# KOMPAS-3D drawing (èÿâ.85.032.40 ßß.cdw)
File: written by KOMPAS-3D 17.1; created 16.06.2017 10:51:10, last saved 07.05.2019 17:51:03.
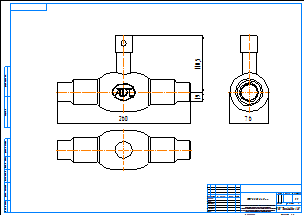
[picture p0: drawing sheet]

Sheet 1: A2, landscape

Title block, sheet 1: name: КШГ.85.032.40 сс; material: Внимание! Данный продукт является объектом авторского права ООО «Торговый Дом АДЛ». / Запрещается изменение, копирование, распространение / (в том числе путем копирования на другие сайты и ресурсы в Интернете) / или любое иное использование информации и объектов без предварительного / согласия правообладателя (ООО «Торговый Дом АДЛ»).; scale: 1:1; sheets: 1; organisation: ООО "Торговый дом АДЛ"; sheet format: A2; stored path: C:\Users\tra\Desktop\2д чертежи\Шаровые краны БИВАЛ\КШ_Бивал_серия_82_85\KOMPAS 2D\КШГ.85.032.40 сс.cdw

Views: Спереди 1, Проекционный вид 2, Проекционный вид 3
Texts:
  Klimkovich
  ADL
Dimensions and other numbers on the sheet: 260; 110,5; 19; 76; 1:1; 1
